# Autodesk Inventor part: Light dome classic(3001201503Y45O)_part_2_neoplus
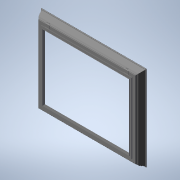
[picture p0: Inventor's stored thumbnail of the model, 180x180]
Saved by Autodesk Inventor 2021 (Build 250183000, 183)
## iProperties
Created: 2026-04
Part Number: Light dome classic(3001201503Y45O)_part_2_neoplus
Material: Generic
Catalog Web Link: www.3dfindit.com
Description: Light dome classic_part_2_neoplus-
Vendor: KINGSPAN
Document SubType Name: Modeling
Designer: psAdmin
Manufacturer: KINGSPAN
Mass: 13007 g
Surface Area: 25647.8 cm^2
Volume: 13007 cm^3
Density: 1 g/cm^3
Appearance: PSOLRGB-255-255-255
Category: PARTsolutions
Company: KINGSPAN
Title: Light dome classic(3001201503Y45O)_part_2_neoplus
Author: Cadenas PARTsolutions
PSOL_IDENT_0: {$CADENAS_DATA/23d-libs/kingspan_kla/light_dome_classic_neoplus/parts/part_2.prj},293 {VTYP=3D},{NB=
PSOL_IDENT_1: Light dome classic(3001201503Y45O)_part_2_neoplus},{LINA=Light dome classic(3001201503Y45O)_part_2_n
PSOL_IDENT_2: eoplus},{NN=Light dome classic_part_2_neoplus},{DATE=20.03.2025 09:30:52},{GEOMDATE=01.07.2024 06:23
PSOL_IDENT_3: :48},{VERSION=},{LINEID=10},{WBVAR=LODLEVEL,L,W,BA,SF,DP,OP,OC},{WBNUMERIC=W}  {NB=Light dome classi
PSOL_IDENT_4: c(3001201503Y45O)_part_2_neoplus},{LINA=Light dome classic(3001201503Y45O)_part_2_neoplus},{KT=DUMMY
PSOL_IDENT_5: },{IDNR=},{PN=Light dome classic},{LODLEVEL=300},{L=120},{W=150},{WX=120,150,180,240,270,300},{LX=12
PSOL_IDENT_6: 00},{XWX=1500},{BA=3},{SF=Y},{SFX='Y','Yes','N','No'},{DRIVE=1},{DPX='1', 'Natural ventilation', '2'
PSOL_IDENT_7: , 'NSHEV (natural smoke, heat exhaust ventilation)', '3', 'Fixed','4','NSHE'},{DP=4},{OPX='5','Pneu
PSOL_IDENT_8: matic - NRWG F.6 LK'},{OP=5},{OCX='O', 'Open', 'C', 'Closed'},{OC=O}
NB: Light dome classic(3001201503Y45O)_part_2_neoplus
NN: Light dome classic_part_2_neoplus
NBSYN: $PN.($LODLEVEL.$L.$W.$BA.$SF.$DP.$OP.$OC.)_part_2_neoplus
LINA: Light dome classic(3001201503Y45O)_part_2_neoplus
CATALOG: Light + Air
PN: Light dome classic
LODLEVEL: 300
L: 120
W: 150
BA: PVC base 50 cm
SF: Yes
DP: NSHE
OP: Pneumatic - NRWG F.6 LK
OC: Open
SUPPLIER: KINGSPAN
ARTICLENO: Light dome classic(3001201503Y45O)_part_2_neoplus
BOMINFO: Light dome classic(3001201503Y45O)_part_2_neoplus
CREATOR: CADENAS GmbH
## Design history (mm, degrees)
sketch "Sketch_1"
  geometry: L1 (-643, 334)-(-645.2, 334); L2 (-645.2, 334)-(-645.2, 327); L3 (-645.2, 327)-(-674, 327); L4 (-674, 327)-(-674, 316); L5 (-674, 316)-(-717.8, 316); L6 (-722, 311.8)-(-722, 306.773); L7 (-727, 298.113)-(-739.32, 291); L8 (-739.32, 291)-(-750.849, 274.535); L9 (-750.849, 274.535)-(-746.754, 271.668); L10 (-746.754, 271.668)-(-758.226, 255.284); L11 (-758.226, 255.284)-(-754.129, 252.415); L12 (-754.129, 252.415)-(-765.6, 236.032); L13 (-765.6, 236.032)-(-761.507, 233.166); L14 (-761.507, 233.166)-(-771.208, 219.311); L15 (-771.208, 219.311)-(-782.773, 219.311); L16 (-782.773, 219.311)-(-782.773, 204.131); L17 (-782.773, 204.131)-(-775.173, 204.131); L18 (-769.959, 217.26)-(-758.443, 233.706); L19 (-758.443, 233.706)-(-762.536, 236.572); L20 (-762.536, 236.572)-(-751.065, 252.955); L21 (-751.065, 252.955)-(-755.162, 255.824); L22 (-755.162, 255.824)-(-743.69, 272.208); L23 (-743.69, 272.208)-(-747.785, 275.075); L24 (-747.785, 275.075)-(-737.798, 289.339); L25 (-737.798, 289.339)-(-731.456, 293); L26 (-731.456, 293)-(-643, 293); L27 (-643, 293)-(-643, 334); A1 r 4.2 centre (-717.8, 311.8) between (-717.8, 316) and (-722, 311.8); A2 r 10 centre (-732, 306.773) between (-727, 298.113) and (-722, 306.773); A3 r 7.6 centre (-775.173, 211.731) between (-775.173, 204.131) and (-769.959, 217.26)
  constraints: 54 end point, 6 point on circle, 3 centre point
extrude "Extrusion1" join sketch "Sketch_1" stored distance "d0" = 2400; taper "d1" = 0 deg
sketch "Sketch_2"
  geometry: L1 (495.2, 334)-(493, 334); L2 (493, 334)-(493, 293); L3 (493, 293)-(581.456, 293); L4 (581.456, 293)-(587.798, 289.339); L5 (587.798, 289.339)-(597.785, 275.075); L6 (597.785, 275.075)-(593.69, 272.208); L7 (593.69, 272.208)-(605.162, 255.824); L8 (605.162, 255.824)-(601.065, 252.955); L9 (601.065, 252.955)-(612.536, 236.572); L10 (612.536, 236.572)-(608.443, 233.706); L11 (608.443, 233.706)-(619.959, 217.26); L12 (625.173, 204.131)-(632.77, 204.131); L13 (632.77, 204.131)-(632.77, 219.311); L14 (632.77, 219.311)-(621.208, 219.311); L15 (621.208, 219.311)-(611.507, 233.166); L16 (611.507, 233.166)-(615.6, 236.032); L17 (615.6, 236.032)-(604.129, 252.415); L18 (604.129, 252.415)-(608.226, 255.284); L19 (608.226, 255.284)-(596.754, 271.668); L20 (596.754, 271.668)-(600.849, 274.535); L21 (600.849, 274.535)-(589.32, 291); L22 (589.32, 291)-(577, 298.113); L23 (572, 306.773)-(572, 311.8); L24 (567.8, 316)-(524, 316); L25 (524, 316)-(524, 327); L26 (524, 327)-(495.2, 327); L27 (495.2, 327)-(495.2, 334); A1 r 7.6 centre (625.173, 211.731) between (619.959, 217.26) and (625.173, 204.131); A2 r 10 centre (582, 306.773) between (572, 306.773) and (577, 298.113); A3 r 4.2 centre (567.8, 311.8) between (572, 311.8) and (567.8, 316)
  constraints: 54 end point, 6 point on circle, 3 centre point
extrude "Extrusion2" join sketch "Sketch_2" stored distance "d2" = 3000; taper "d3" = 0 deg
sketch "Sketch_3"
  geometry: L1 (784.773, 204.131)-(784.773, 219.311); L2 (784.773, 219.311)-(771.208, 219.311); L3 (771.208, 219.311)-(761.507, 233.166); L4 (761.507, 233.166)-(765.6, 236.032); L5 (765.6, 236.032)-(754.129, 252.415); L6 (754.129, 252.415)-(758.226, 255.284); L7 (758.226, 255.284)-(746.754, 271.668); L8 (746.754, 271.668)-(750.849, 274.535); L9 (750.849, 274.535)-(739.32, 291); L10 (739.32, 291)-(727, 298.113); L11 (722, 306.773)-(722, 311.8); L12 (717.8, 316)-(674, 316); L13 (674, 316)-(674, 327); L14 (674, 327)-(645.2, 327); L15 (645.2, 327)-(645.2, 334); L16 (645.2, 334)-(643, 334); L17 (643, 334)-(643, 293); L18 (643, 293)-(731.456, 293); L19 (731.456, 293)-(737.798, 289.339); L20 (737.798, 289.339)-(747.785, 275.075); L21 (747.785, 275.075)-(743.69, 272.208); L22 (743.69, 272.208)-(755.162, 255.824); L23 (755.162, 255.824)-(751.065, 252.955); L24 (751.065, 252.955)-(762.536, 236.572); L25 (762.536, 236.572)-(758.443, 233.706); L26 (758.443, 233.706)-(769.959, 217.26); L27 (775.173, 204.131)-(784.773, 204.131); A1 r 10 centre (732, 306.773) between (722, 306.773) and (727, 298.113); A2 r 4.2 centre (717.8, 311.8) between (722, 311.8) and (717.8, 316); A3 r 7.6 centre (775.173, 211.731) between (769.959, 217.26) and (775.173, 204.131)
  constraints: 54 end point, 6 point on circle, 3 centre point
extrude "Extrusion3" join sketch "Sketch_3" stored distance "d4" = 2400; taper "d5" = 0 deg
sketch "Sketch_4"
  geometry: L1 (-495.2, 334)-(-495.2, 327); L2 (-495.2, 327)-(-524, 327); L3 (-524, 327)-(-524, 316); L4 (-524, 316)-(-567.8, 316); L5 (-572, 311.8)-(-572, 306.773); L6 (-577, 298.113)-(-589.32, 291); L7 (-589.32, 291)-(-600.849, 274.535); L8 (-600.849, 274.535)-(-596.754, 271.668); L9 (-596.754, 271.668)-(-608.226, 255.284); L10 (-608.226, 255.284)-(-604.129, 252.415); L11 (-604.129, 252.415)-(-615.6, 236.032); L12 (-615.6, 236.032)-(-611.507, 233.166); L13 (-611.507, 233.166)-(-621.208, 219.311); L14 (-621.208, 219.311)-(-632.77, 219.311); L15 (-632.77, 219.311)-(-632.77, 204.131); L16 (-632.77, 204.131)-(-625.173, 204.131); L17 (-619.959, 217.26)-(-608.443, 233.706); L18 (-608.443, 233.706)-(-612.536, 236.572); L19 (-612.536, 236.572)-(-601.065, 252.955); L20 (-601.065, 252.955)-(-605.162, 255.824); L21 (-605.162, 255.824)-(-593.69, 272.208); L22 (-593.69, 272.208)-(-597.785, 275.075); L23 (-597.785, 275.075)-(-587.798, 289.339); L24 (-587.798, 289.339)-(-581.456, 293); L25 (-581.456, 293)-(-493, 293); L26 (-493, 293)-(-493, 334); L27 (-493, 334)-(-495.2, 334); A1 r 4.2 centre (-567.8, 311.8) between (-567.8, 316) and (-572, 311.8); A2 r 10 centre (-582, 306.773) between (-577, 298.113) and (-572, 306.773); A3 r 7.6 centre (-625.173, 211.731) between (-625.173, 204.131) and (-619.959, 217.26)
  constraints: 54 end point, 6 point on circle, 3 centre point
extrude "Extrusion4" join sketch "Sketch_4" stored distance "d6" = 3000; taper "d7" = 0 deg
sketch "Sketch_5"
  geometry: L1 (-643, 357)-(-1593, 357); L2 (-1593, 357)-(-1593, 36.767); L3 (-1593, 36.767)-(-777.437, 180.866); L4 (-777.437, 180.866)-(-782.657, 210.409); L5 (-775.724, 219.311)-(-771.208, 219.311); L6 (-771.208, 219.311)-(-761.507, 233.166); L7 (-761.507, 233.166)-(-765.6, 236.032); L8 (-765.6, 236.032)-(-754.129, 252.415); L9 (-754.129, 252.415)-(-758.226, 255.284); L10 (-758.226, 255.284)-(-746.754, 271.668); L11 (-746.754, 271.668)-(-750.849, 274.535); L12 (-750.849, 274.535)-(-739.32, 291); L13 (-739.32, 291)-(-727, 298.113); L14 (-722, 306.773)-(-722, 311.8); L15 (-717.8, 316)-(-674, 316); L16 (-674, 316)-(-674, 327); L17 (-674, 327)-(-645.2, 327); L18 (-645.2, 327)-(-645.2, 334); L19 (-645.2, 334)-(-643, 334); L20 (-643, 334)-(-643, 357); A1 r 7.6 centre (-775.173, 211.731) between (-775.724, 219.311) and (-782.657, 210.409); A2 r 10 centre (-732, 306.773) between (-727, 298.113) and (-722, 306.773); A3 r 4.2 centre (-717.8, 311.8) between (-717.8, 316) and (-722, 311.8)
  constraints: 40 end point, 6 point on circle, 3 centre point
extrude "Extrusion5" cut sketch "Sketch_5" stored distance "d8" = 2400; taper "d9" = 0 deg
sketch "Sketch_6"
  geometry: L1 (1593, 36.767)-(1593, 357); L2 (1593, 357)-(643, 357); L3 (643, 357)-(643, 334); L4 (643, 334)-(645.2, 334); L5 (645.2, 334)-(645.2, 327); L6 (645.2, 327)-(674, 327); L7 (674, 327)-(674, 316); L8 (674, 316)-(717.8, 316); L9 (722, 311.8)-(722, 306.773); L10 (727, 298.113)-(739.32, 291); L11 (739.32, 291)-(750.849, 274.535); L12 (750.849, 274.535)-(746.754, 271.668); L13 (746.754, 271.668)-(758.226, 255.284); L14 (758.226, 255.284)-(754.129, 252.415); L15 (754.129, 252.415)-(765.6, 236.032); L16 (765.6, 236.032)-(761.507, 233.166); L17 (761.507, 233.166)-(771.208, 219.311); L18 (771.208, 219.311)-(775.724, 219.311); L19 (782.657, 210.409)-(777.437, 180.866); L20 (777.437, 180.866)-(1593, 36.767); A1 r 4.2 centre (717.8, 311.8) between (722, 311.8) and (717.8, 316); A2 r 10 centre (732, 306.773) between (722, 306.773) and (727, 298.113); A3 r 7.6 centre (775.173, 211.731) between (782.657, 210.409) and (775.724, 219.311)
  constraints: 40 end point, 6 point on circle, 3 centre point
extrude "Extrusion6" cut sketch "Sketch_6" stored distance "d10" = 3000; taper "d11" = 0 deg
sketch "Sketch_7"
  geometry: L1 (493, 357)-(493, 334); L2 (493, 334)-(495.2, 334); L3 (495.2, 334)-(495.2, 327); L4 (495.2, 327)-(524, 327); L5 (524, 327)-(524, 316); L6 (524, 316)-(567.8, 316); L7 (572, 311.8)-(572, 306.773); L8 (577, 298.113)-(589.32, 291); L9 (589.32, 291)-(600.849, 274.535); L10 (600.849, 274.535)-(596.754, 271.668); L11 (596.754, 271.668)-(608.226, 255.284); L12 (608.226, 255.284)-(604.129, 252.415); L13 (604.129, 252.415)-(615.6, 236.032); L14 (615.6, 236.032)-(611.507, 233.166); L15 (611.507, 233.166)-(621.208, 219.311); L16 (621.208, 219.311)-(625.724, 219.311); L17 (632.657, 210.409)-(623.957, 161.171); L18 (623.957, 161.171)-(1293, 42.96); L19 (1293, 42.96)-(1293, 357); L20 (1293, 357)-(493, 357); A1 r 4.2 centre (567.8, 311.8) between (572, 311.8) and (567.8, 316); A2 r 10 centre (582, 306.773) between (572, 306.773) and (577, 298.113); A3 r 7.6 centre (625.173, 211.731) between (632.657, 210.409) and (625.724, 219.311)
  constraints: 40 end point, 6 point on circle, 3 centre point
extrude "Extrusion7" cut sketch "Sketch_7" stored distance "d12" = 3000; taper "d13" = 0 deg
sketch "Sketch_8"
  geometry: L1 (-493, 357)-(-1293, 357); L2 (-1293, 357)-(-1293, 42.96); L3 (-1293, 42.96)-(-623.957, 161.171); L4 (-623.957, 161.171)-(-632.657, 210.409); L5 (-625.724, 219.311)-(-621.208, 219.311); L6 (-621.208, 219.311)-(-611.507, 233.166); L7 (-611.507, 233.166)-(-615.6, 236.032); L8 (-615.6, 236.032)-(-604.129, 252.415); L9 (-604.129, 252.415)-(-608.226, 255.284); L10 (-608.226, 255.284)-(-596.754, 271.668); L11 (-596.754, 271.668)-(-600.849, 274.535); L12 (-600.849, 274.535)-(-589.32, 291); L13 (-589.32, 291)-(-577, 298.113); L14 (-572, 306.773)-(-572, 311.8); L15 (-567.8, 316)-(-524, 316); L16 (-524, 316)-(-524, 327); L17 (-524, 327)-(-495.2, 327); L18 (-495.2, 327)-(-495.2, 334); L19 (-495.2, 334)-(-493, 334); L20 (-493, 334)-(-493, 357); A1 r 7.6 centre (-625.173, 211.731) between (-625.724, 219.311) and (-632.657, 210.409); A2 r 10 centre (-582, 306.773) between (-577, 298.113) and (-572, 306.773); A3 r 4.2 centre (-567.8, 311.8) between (-567.8, 316) and (-572, 311.8)
  constraints: 40 end point, 6 point on circle, 3 centre point
extrude "Extrusion8" cut sketch "Sketch_8" stored distance "d14" = 3000; taper "d15" = 0 deg
sketch "Sketch_13"
  geometry: L1 (-319.461, 525.103)-(-318, 525); L2 (-318, 525)-(-316, 525); L3 (-316, 525)-(-316, 574.531); L4 (-316, 574.531)-(-303.205, 584.473); L5 (-308.009, 583.974)-(-307.436, 585.954); L6 (-304.441, 586.046)-(-318, 575.51); L7 (-318, 575.51)-(-318, 529); L8 (-318, 529)-(-319.461, 525.103); A1 r 4.5 centre (-306, 588) between (-303.205, 584.473) and (-308.009, 583.974); A2 r 2.5 centre (-306, 588) between (-304.441, 586.046) and (-307.436, 585.954)
  constraints: 16 end point, 4 point on circle, 2 centre point
extrude "Extrusion9" join sketch "Sketch_13" distance "d16" = 70; taper "d17" = 0 deg
sketch "Sketch_14"
  geometry: L1 (-319.461, 525.103)-(-318, 525); L2 (-318, 525)-(-316, 525); L3 (-316, 525)-(-316, 574.531); L4 (-316, 574.531)-(-303.205, 584.473); L5 (-308.009, 583.974)-(-307.436, 585.954); L6 (-304.441, 586.046)-(-318, 575.51); L7 (-318, 575.51)-(-318, 529); L8 (-318, 529)-(-319.461, 525.103); A1 r 4.5 centre (-306, 588) between (-303.205, 584.473) and (-308.009, 583.974); A2 r 2.5 centre (-306, 588) between (-304.441, 586.046) and (-307.436, 585.954)
  constraints: 16 end point, 4 point on circle, 2 centre point
extrude "Extrusion10" join sketch "Sketch_14" distance "d18" = 70; taper "d19" = 0 deg
sketch "Sketch_15"
  geometry: L1 (549, 602.5)-(549, 581.42); L2 (549, 581.42)-(567.5, 581.42); L3 (567.5, 581.42)-(567.5, 592.5); L4 (567.5, 592.5)-(600.5, 592.5); L5 (600.5, 592.5)-(600.5, 581.42); L6 (600.5, 581.42)-(619, 581.42); L7 (619, 581.42)-(619, 602.5); L8 (619, 602.5)-(549, 602.5)
  constraints: 16 end point
extrude "Extrusion11" cut sketch "Sketch_15" distance "d20" = 20; taper "d21" = 0 deg
sketch "Sketch_16"
  geometry: L1 (-619, 581.42)-(-600.5, 581.42); L2 (-600.5, 581.42)-(-600.5, 592.5); L3 (-600.5, 592.5)-(-567.5, 592.5); L4 (-567.5, 592.5)-(-567.5, 581.42); L5 (-567.5, 581.42)-(-549, 581.42); L6 (-549, 581.42)-(-549, 602.5); L7 (-549, 602.5)-(-619, 602.5); L8 (-619, 602.5)-(-619, 581.42)
  constraints: 16 end point
extrude "Extrusion12" cut sketch "Sketch_16" distance "d22" = 20; taper "d23" = 0 deg
sketch "Sketch_21"
  geometry: L1 (-771.208, 224.311)-(-805.173, 224.311); L2 (-805.173, 224.311)-(-805.173, 189.311); L3 (-805.173, 189.311)-(-775.173, 189.311); L4 (-775.173, 189.311)-(-775.173, 204.131); L5 (-775.724, 219.311)-(-771.208, 219.311); L6 (-771.208, 219.311)-(-771.208, 224.311); A1 r 7.6 centre (-775.173, 211.731) between (-775.724, 219.311) and (-775.173, 204.131)
  constraints: 12 end point, 2 point on circle, 1 centre point
extrude "Extrusion13" cut sketch "Sketch_21" stored distance "d24" = 3000; taper "d25" = 0 deg
sketch "Sketch_22"
  geometry: L1 (805.173, 224.311)-(771.208, 224.311); L2 (771.208, 224.311)-(771.208, 219.311); L3 (771.208, 219.311)-(775.724, 219.311); L4 (775.173, 204.131)-(775.173, 189.311); L5 (775.173, 189.311)-(805.173, 189.311); L6 (805.173, 189.311)-(805.173, 224.311); A1 r 7.6 centre (775.173, 211.731) between (775.173, 204.131) and (775.724, 219.311)
  constraints: 12 end point, 2 point on circle, 1 centre point
extrude "Extrusion14" cut sketch "Sketch_22" stored distance "d26" = 3000; taper "d27" = 0 deg
sketch "Sketch_23"
  geometry: L1 (621.208, 224.311)-(621.208, 219.311); L2 (621.208, 219.311)-(625.724, 219.311); L3 (625.173, 204.131)-(625.173, 189.311); L4 (625.173, 189.311)-(642.77, 189.311); L5 (642.77, 189.311)-(642.77, 224.311); L6 (642.77, 224.311)-(621.208, 224.311); A1 r 7.6 centre (625.173, 211.731) between (625.173, 204.131) and (625.724, 219.311)
  constraints: 12 end point, 2 point on circle, 1 centre point
extrude "Extrusion15" cut sketch "Sketch_23" stored distance "d28" = 3000; taper "d29" = 0 deg
sketch "Sketch_24"
  geometry: L1 (-621.208, 224.311)-(-642.77, 224.311); L2 (-642.77, 224.311)-(-642.77, 189.311); L3 (-642.77, 189.311)-(-625.173, 189.311); L4 (-625.173, 189.311)-(-625.173, 204.131); L5 (-625.724, 219.311)-(-621.208, 219.311); L6 (-621.208, 219.311)-(-621.208, 224.311); A1 r 7.6 centre (-625.173, 211.731) between (-625.724, 219.311) and (-625.173, 204.131)
  constraints: 12 end point, 2 point on circle, 1 centre point
extrude "Extrusion16" cut sketch "Sketch_24" stored distance "d30" = 3000; taper "d31" = 0 deg
node "IP_2_XY"
node "IP_2_YZ"
node "IP_2_ZX"
node "IP_2_X"
node "IP_2_Y"
node "IP_2_Z"
node "IP_2_Center"
node "IP_for_part_3_XY"
node "IP_for_part_3_YZ"
node "IP_for_part_3_ZX"
node "IP_for_part_3_X"
node "IP_for_part_3_Y"
node "IP_for_part_3_Z"
node "IP_for_part_3_Center"
node "IP_for_part_8_1_XY"
node "IP_for_part_8_1_YZ"
node "IP_for_part_8_1_ZX"
node "IP_for_part_8_1_X"
node "IP_for_part_8_1_Y"
node "IP_for_part_8_1_Z"
node "IP_for_part_8_1_Center"
node "IP_for_part_8_2_XY"
node "IP_for_part_8_2_YZ"
node "IP_for_part_8_2_ZX"
node "IP_for_part_8_2_X"
node "IP_for_part_8_2_Y"
node "IP_for_part_8_2_Z"
node "IP_for_part_8_2_Center"
node "IP_for_part_8_3_XY"
node "IP_for_part_8_3_YZ"
node "IP_for_part_8_3_ZX"
node "IP_for_part_8_3_X"
node "IP_for_part_8_3_Y"
node "IP_for_part_8_3_Z"
node "IP_for_part_8_3_Center"
node "IP_for_part_8_4_XY"
node "IP_for_part_8_4_YZ"
node "IP_for_part_8_4_ZX"
node "IP_for_part_8_4_X"
node "IP_for_part_8_4_Y"
node "IP_for_part_8_4_Z"
node "IP_for_part_8_4_Center"
node "IP_for_part_8_5_XY"
node "IP_for_part_8_5_YZ"
node "IP_for_part_8_5_ZX"
node "IP_for_part_8_5_X"
node "IP_for_part_8_5_Y"
node "IP_for_part_8_5_Z"
node "IP_for_part_8_5_Center"
node "IP_for_part_9_XY"
node "IP_for_part_9_YZ"
node "IP_for_part_9_ZX"
node "IP_for_part_9_X"
node "IP_for_part_9_Y"
node "IP_for_part_9_Z"
node "IP_for_part_9_Center"
body "Solid1"
other parameters: "d32" = 0
